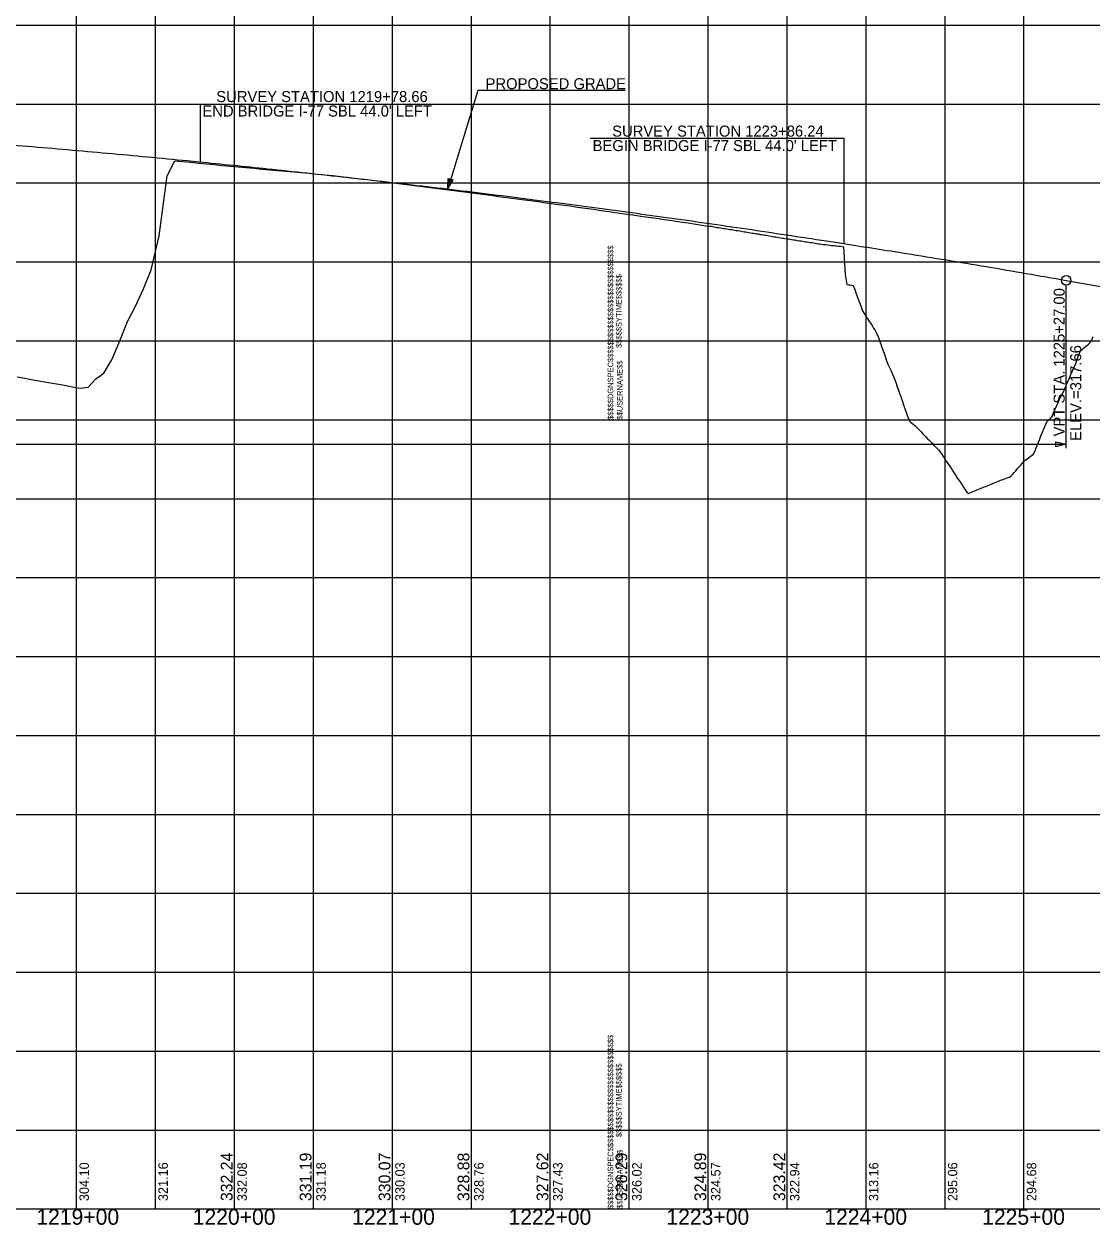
# Model space of a CAD drawing. Extents: x -90830 to 2015517, y -20856 to 836331.
# Drawn here: x 10790 to 11467, y -10807 to -10046 of the extents above; entities that cross this region are included whole.
import ezdxf

# ---------------------------------------------------------------- set-up
doc = ezdxf.new("R2010")
doc.units = 0
for name, color, linetype in [('Level 1', 7, 'Continuous'), ('RD_DDB_Profile_Elev', 7, 'Continuous'), ('RD_DDB_Profile_EX', 7, 'Continuous'), ('RD_DDB_Profile_Lbl', 7, 'Continuous'), ('RD_DDB_Profile_PR', 7, 'Continuous'), ('RD_DDB_StaTX', 7, 'Continuous'), ('RD_DDB_StripGrade', 7, 'Continuous'), ('RD_DDB_VCLbl', 7, 'Continuous'), ('RD_GPK_Profile_Cell', 7, 'Continuous'), ('RD_PD_Final_TX', 7, 'Continuous'), ('RD_TX_Drainage', 7, 'Continuous')]:
    doc.layers.add(name, color=color, linetype=linetype)

msp = doc.modelspace()

# ---------------------------------------------------------------- linework, layer by layer
at = {"layer": 'Level 1'}
for p, q in [((10823.46, -9797.12), (10823.46, -10297.12)), ((10873.46, -9797.12), (10873.46, -10297.12)), ((10923.46, -9797.12), (10923.46, -10297.12)), ((10973.46, -9797.12), (10973.46, -10297.12)), ((11023.46, -9797.12), (11023.46, -10297.12)), ((11073.46, -9797.12), (11073.46, -10297.12)), ((11123.46, -9797.12), (11123.46, -10297.12)), ((11173.46, -9797.12), (11173.46, -10297.12)), ((11173.46, -9797.12), (11173.46, -10297.12)), ((11173.46, -9797.12), (11173.46, -10297.12)), ((11223.46, -9797.12), (11223.46, -10297.12)), ((11273.46, -9797.12), (11273.46, -10297.12)), ((11323.46, -9797.12), (11323.46, -10297.12)), ((11373.46, -9797.12), (11373.46, -10297.12)), ((11423.46, -9797.12), (11423.46, -10297.12)), ((9573.46, -10047.12), (11173.46, -10047.12)), ((11173.46, -10047.12), (12773.46, -10047.12)), ((9573.46, -10097.12), (11173.46, -10097.12)), ((11173.46, -10097.12), (12773.46, -10097.12)), ((9573.46, -10147.12), (11173.46, -10147.12)), ((11173.46, -10147.12), (12773.46, -10147.12)), ((9573.46, -10197.12), (11173.46, -10197.12)), ((11173.46, -10197.12), (12773.46, -10197.12)), ((9573.46, -10247.12), (11173.46, -10247.12)), ((11173.46, -10247.12), (12773.46, -10247.12)), ((9573.46, -10297.12), (11173.46, -10297.12)), ((9573.46, -10297.12), (11173.46, -10297.12)), ((10823.46, -10297.12), (10823.46, -10797.12)), ((10873.46, -10297.12), (10873.46, -10797.12)), ((10923.46, -10297.12), (10923.46, -10797.12)), ((10973.46, -10297.12), (10973.46, -10797.12)), ((11023.46, -10297.12), (11023.46, -10797.12)), ((11073.46, -10297.12), (11073.46, -10797.12)), ((11123.46, -10297.12), (11123.46, -10797.12)), ((11173.46, -10297.12), (11173.46, -10797.12)), ((11173.46, -10297.12), (11173.46, -10797.12)), ((11173.46, -10297.12), (12773.46, -10297.12)), ((11173.46, -10297.12), (12773.46, -10297.12)), ((11173.46, -10297.12), (11173.46, -10797.12)), ((11223.46, -10297.12), (11223.46, -10797.12)), ((11273.46, -10297.12), (11273.46, -10797.12)), ((11323.46, -10297.12), (11323.46, -10797.12)), ((11373.46, -10297.12), (11373.46, -10797.12)), ((11423.46, -10297.12), (11423.46, -10797.12)), ((9573.46, -10347.12), (11173.46, -10347.12)), ((11173.46, -10347.12), (12773.46, -10347.12)), ((9573.46, -10397.12), (11173.46, -10397.12)), ((11173.46, -10397.12), (12773.46, -10397.12)), ((9573.46, -10447.12), (11173.46, -10447.12)), ((11173.46, -10447.12), (12773.46, -10447.12)), ((9573.46, -10497.12), (11173.46, -10497.12)), ((11173.46, -10497.12), (12773.46, -10497.12)), ((9573.46, -10547.12), (11173.46, -10547.12)), ((11173.46, -10547.12), (12773.46, -10547.12)), ((9573.46, -10597.12), (11173.46, -10597.12)), ((11173.46, -10597.12), (12773.46, -10597.12)), ((9573.46, -10647.12), (11173.46, -10647.12)), ((11173.46, -10647.12), (12773.46, -10647.12)), ((9573.46, -10697.12), (11173.46, -10697.12)), ((11173.46, -10697.12), (12773.46, -10697.12)), ((9573.46, -10747.12), (11173.46, -10747.12)), ((11173.46, -10747.12), (12773.46, -10747.12)), ((9573.46, -10797.12), (11173.46, -10797.12)), ((11173.46, -10797.12), (12773.46, -10797.12))]:
    msp.add_line(p, q, dxfattribs=at)
at = {"layer": 'RD_DDB_Profile_EX'}
for points in [[(10785.95, -10270.03), (10790.95, -10270.85), (10795.95, -10271.77), (10800.95, -10272.7), (10805.95, -10273.55), (10810.95, -10274.39), (10815.95, -10275.27), (10820.95, -10276.19), (10825.95, -10277.02), (10830.95, -10276.53), (10835.95, -10271.22), (10840.95, -10267.62), (10845.95, -10259.08), (10850.95, -10247.21), (10855.95, -10234.96), (10860.95, -10225.23), (10865.95, -10214.2), (10870.95, -10202.1), (10875.95, -10180.59), (10880.95, -10142.52), (10885.95, -10133), (10890.95, -10133.5), (10895.95, -10134), (10900.95, -10134.51), (10905.95, -10135.01), (10910.95, -10135.49), (10915.95, -10135.98), (10920.95, -10136.47), (10925.95, -10136.94), (10930.95, -10137.4), (10935.95, -10137.84), (10940.95, -10138.29), (10945.95, -10138.74), (10950.95, -10139.17), (10955.95, -10139.61), (10960.95, -10140.04), (10965.95, -10140.5), (10970.95, -10140.98), (10975.95, -10141.47), (10980.95, -10141.97), (10985.95, -10142.48), (10990.95, -10143.06), (10995.95, -10143.63), (11000.95, -10144.2), (11005.95, -10144.78), (11010.95, -10145.4), (11015.95, -10146.02), (11020.95, -10146.66), (11025.95, -10147.29), (11030.95, -10147.91), (11035.95, -10148.54), (11040.95, -10149.16), (11045.95, -10149.78)], [(11045.95, -10149.78), (11050.95, -10150.42), (11055.95, -10151.06), (11060.95, -10151.7), (11065.95, -10152.35), (11070.95, -10152.99), (11075.95, -10153.63), (11080.95, -10154.27), (11085.95, -10154.92), (11090.95, -10155.58), (11095.95, -10156.24), (11100.95, -10156.91), (11105.95, -10157.57), (11110.95, -10158.25), (11115.95, -10158.92), (11120.95, -10159.6), (11125.95, -10160.29), (11130.95, -10160.98), (11135.95, -10161.67), (11140.95, -10162.37), (11145.95, -10163.07), (11150.95, -10163.78), (11155.95, -10164.5), (11160.95, -10165.23), (11165.95, -10165.95), (11170.95, -10166.66), (11175.95, -10167.36), (11180.95, -10168.05), (11185.95, -10168.75), (11190.95, -10169.46), (11195.95, -10170.19), (11200.95, -10170.92), (11205.95, -10171.66), (11210.95, -10172.41), (11215.95, -10173.2), (11223.46, -10174.38)], [(11223.46, -10174.29), (11224.46, -10174.44), (11225.46, -10174.58), (11226.46, -10174.79), (11227.46, -10174.98), (11228.46, -10175.09), (11229.46, -10175.22), (11230.46, -10175.43), (11231.46, -10175.59), (11232.46, -10175.71), (11233.46, -10175.89), (11234.46, -10176.04), (11235.46, -10176.18), (11236.46, -10176.33), (11237.46, -10176.53), (11238.46, -10176.68), (11239.46, -10176.87), (11240.46, -10177.02), (11241.46, -10177.16), (11242.46, -10177.32), (11243.46, -10177.41), (11244.46, -10177.61), (11245.46, -10177.95), (11246.46, -10178.05), (11247.46, -10178.1), (11248.46, -10178.34), (11249.46, -10178.45), (11250.46, -10178.68), (11251.46, -10178.83), (11252.46, -10178.94), (11253.46, -10179.13), (11254.46, -10179.28), (11255.46, -10179.44), (11256.46, -10179.67), (11257.46, -10179.79), (11258.46, -10179.93), (11259.46, -10180.16), (11260.46, -10180.28), (11261.46, -10180.47), (11262.46, -10180.63), (11263.46, -10180.85), (11264.46, -10180.99), (11265.46, -10181.16), (11266.46, -10181.32), (11267.46, -10181.47), (11268.46, -10181.63), (11269.46, -10181.83), (11270.46, -10181.99), (11271.46, -10182.08), (11272.46, -10182.24), (11273.46, -10182.42), (11274.46, -10182.61), (11275.46, -10182.74), (11276.46, -10182.87), (11277.46, -10183.09), (11278.46, -10183.24), (11279.46, -10183.43), (11280.46, -10183.57), (11281.46, -10183.71), (11282.46, -10183.82), (11283.46, -10184.01), (11284.46, -10184.16), (11285.46, -10184.31), (11286.46, -10184.49), (11287.46, -10184.6), (11288.46, -10184.78), (11289.46, -10184.88), (11290.46, -10185.08), (11291.46, -10185.27), (11292.46, -10185.42), (11293.46, -10185.57), (11294.46, -10185.71), (11295.46, -10185.86), (11296.46, -10186), (11297.46, -10186.1), (11298.46, -10186.2), (11299.46, -10186.35), (11300.46, -10186.45), (11301.46, -10186.63), (11302.46, -10186.74), (11303.46, -10186.8), (11304.46, -10186.93), (11305.46, -10186.92), (11306.46, -10187.08), (11307.46, -10187.25), (11308.46, -10187.39), (11309.46, -10187.51), (11310.46, -10205.14), (11311.46, -10211.45), (11312.46, -10211.58), (11313.46, -10211.71), (11314.46, -10211.84), (11315.46, -10211.97), (11316.46, -10214.55), (11317.46, -10217.33), (11318.46, -10220.12), (11319.46, -10222.9), (11320.46, -10225.69), (11321.46, -10228.22), (11322.46, -10229.76), (11323.46, -10231.3)], [(11323.46, -10231.3), (11324.46, -10232.85), (11325.46, -10234.39), (11326.46, -10235.93), (11327.46, -10237.47), (11328.46, -10239.01), (11329.46, -10240.55), (11330.46, -10242.68), (11331.46, -10245.08), (11332.46, -10247.5), (11333.46, -10250.44), (11334.46, -10253.37), (11335.46, -10256.3), (11336.46, -10259.11), (11337.46, -10261.84), (11338.46, -10264.03), (11339.46, -10266.13), (11340.46, -10268.23), (11341.46, -10270.88), (11342.46, -10273.61), (11343.46, -10276.33), (11344.46, -10279.09), (11345.46, -10281.97), (11346.46, -10284.86), (11347.46, -10287.74), (11348.46, -10290.65), (11349.46, -10293.56), (11350.46, -10296.48), (11351.46, -10298.13), (11352.46, -10298.98), (11353.46, -10299.82), (11354.46, -10300.66), (11355.46, -10301.64), (11356.46, -10302.68), (11357.46, -10303.72), (11358.46, -10304.75), (11359.46, -10305.79), (11360.46, -10306.83), (11361.46, -10307.87), (11362.46, -10308.91), (11363.46, -10309.95), (11364.46, -10310.99), (11365.46, -10312.03), (11366.46, -10313.07), (11367.46, -10314.11), (11368.46, -10315.15), (11369.46, -10316.19), (11370.46, -10317.29), (11371.46, -10318.8), (11372.46, -10320.3), (11373.46, -10321.81), (11374.46, -10323.32), (11375.46, -10324.83), (11376.46, -10326.34), (11377.46, -10327.85), (11378.46, -10329.35), (11379.46, -10330.86), (11380.46, -10332.37), (11381.46, -10333.88), (11382.46, -10335.39), (11383.46, -10336.89), (11384.46, -10338.4), (11385.46, -10339.91), (11386.46, -10341.42), (11387.46, -10342.92), (11388.46, -10343.94), (11389.46, -10343.5), (11390.46, -10343.07), (11391.46, -10342.62), (11392.46, -10342.16), (11393.46, -10341.75), (11394.46, -10341.34), (11395.46, -10340.94), (11396.46, -10340.53), (11397.46, -10340.12), (11398.46, -10339.72), (11399.46, -10339.31), (11400.46, -10338.9), (11401.46, -10338.5), (11402.46, -10338.09), (11403.46, -10337.68), (11404.46, -10337.28), (11405.46, -10336.87), (11406.46, -10336.46), (11407.46, -10336.05), (11408.46, -10335.65), (11409.46, -10335.25), (11410.46, -10334.88), (11411.46, -10334.51), (11412.46, -10334.15), (11413.46, -10333.78), (11414.46, -10333.42), (11415.46, -10332.93), (11416.46, -10331.78), (11417.46, -10330.63), (11418.46, -10329.47), (11419.46, -10328.32), (11420.46, -10327.17), (11421.46, -10326.02), (11422.46, -10324.86), (11423.46, -10323.71)], [(11423.46, -10323.71), (11424.46, -10322.75), (11425.46, -10322.03), (11426.46, -10321.3), (11427.46, -10320.58), (11428.46, -10319.85), (11429.46, -10319.12), (11430.46, -10317.33), (11431.46, -10314.84), (11432.46, -10312.36), (11433.46, -10309.87), (11434.46, -10307.39), (11435.46, -10304.9), (11436.46, -10302.42), (11437.46, -10299.93), (11438.46, -10297.97), (11439.46, -10297.19), (11440.46, -10296.41), (11441.46, -10295.07), (11442.46, -10292.75), (11443.46, -10290.42), (11444.46, -10288.1), (11445.46, -10285.78), (11446.46, -10283.48), (11447.46, -10281.75), (11448.46, -10279.85), (11449.46, -10277.55), (11450.46, -10275.25), (11451.46, -10272.96), (11452.46, -10270.66), (11453.46, -10268.36), (11454.46, -10266.06), (11455.46, -10263.76), (11456.46, -10261.46), (11457.46, -10258.8), (11458.46, -10256.1), (11459.46, -10253.48), (11460.46, -10252.63), (11461.46, -10251.78), (11462.46, -10250.93), (11463.46, -10250.09), (11464.46, -10249.24), (11465.46, -10248.39), (11466.46, -10247.15), (11467.46, -10244.4)]]:
    msp.add_lwpolyline(points, dxfattribs=at)
at = {"layer": 'RD_DDB_Profile_Lbl'}
for p, q in [((10902.12, -10097.12), (11053.25, -10097.12)), ((10902.12, -10133.67), (10902.12, -10097.12)), ((11148.92, -10118.75), (11309.7, -10118.75)), ((11309.7, -10185.54), (11309.7, -10118.75))]:
    msp.add_line(p, q, dxfattribs=at)
at = {"layer": 'RD_DDB_Profile_PR'}
msp.add_line((11450.46, -10208.8), (11473.43, -10212.82), dxfattribs=at)
for points in [[(10543.1, -10107.4), (10590.26, -10109.84), (10640.86, -10112.8), (10691.46, -10116.12), (10742.06, -10119.8), (10792.66, -10123.83), (10843.26, -10128.22), (10893.86, -10132.97), (10901.04, -10133.67)], [(10901.04, -10133.67), (10944.46, -10138.08), (10995.06, -10143.54), (11045.66, -10149.36), (11096.26, -10155.54), (11146.86, -10162.08), (11197.46, -10168.97), (11248.06, -10176.22), (11298.66, -10183.83), (11309.7, -10185.54)], [(11309.7, -10185.54), (11349.26, -10191.79), (11399.86, -10200.12), (11450.46, -10208.8)]]:
    msp.add_spline(points, degree=3, dxfattribs=at)
at = {"layer": 'RD_DDB_VCLbl'}
for p, q in [((11450.46, -10315.16), (11450.46, -10211.8)), ((8920.46, -10312.66), (11450.46, -10312.66))]:
    msp.add_line(p, q, dxfattribs=at)
msp.add_circle((11450.46, -10208.8), 3, dxfattribs=at)
at = {"layer": 'RD_GPK_Profile_Cell'}
msp.add_line((4823.46, -10797.12), (75223.46, -10797.12), dxfattribs=at)
at = {"layer": 'RD_PD_Final_TX'}
for p, q in [((11058.69, -10150.92), (11059.03, -10144.25)), ((11060.58, -10144.72), (11058.69, -10150.92)), ((11058.69, -10150.92), (11062.13, -10145.19)), ((11059.03, -10144.25), (11062.13, -10145.19))]:
    msp.add_line(p, q, dxfattribs=at)
for points in [[(11171.13, -10088.55), (11077.74, -10088.55), (11058.69, -10150.92)], [(11060.51, -10144.78), (11058.75, -10150.55), (11060.48, -10144.73), (11058.78, -10150.27), (11060.41, -10144.74), (11058.78, -10150.07), (11060.33, -10144.73), (11058.79, -10149.84), (11060.27, -10144.7), (11058.81, -10149.48), (11060.19, -10144.66), (11058.84, -10149.1), (11060.1, -10144.66), (11058.86, -10148.81), (11060.04, -10144.63), (11058.88, -10148.48), (11059.97, -10144.64), (11058.9, -10148.19), (11059.92, -10144.57), (11058.9, -10147.94), (11059.82, -10144.57), (11058.92, -10147.58), (11059.75, -10144.54), (11058.96, -10147.14), (11059.67, -10144.5), (11058.94, -10146.84), (11059.6, -10144.48), (11058.97, -10146.39), (11059.51, -10144.48), (11059.01, -10146.02), (11059.43, -10144.41), (11059.02, -10145.7), (11059.36, -10144.42), (11059.03, -10145.41), (11059.3, -10144.36), (11059.06, -10145.05), (11059.22, -10144.39), (11059.08, -10144.65), (11059.13, -10144.39)], [(11058.85, -10150.53), (11060.6, -10144.81), (11058.96, -10150.34), (11060.68, -10144.83), (11059.05, -10150.16), (11060.74, -10144.82), (11059.17, -10150), (11060.78, -10144.85), (11059.3, -10149.8), (11060.85, -10144.86), (11059.42, -10149.61), (11060.9, -10144.88), (11059.55, -10149.38), (11060.97, -10144.88), (11059.71, -10149.11), (11061.06, -10144.92), (11059.84, -10148.87), (11061.12, -10144.91), (11059.98, -10148.62), (11061.18, -10144.95), (11060.14, -10148.39), (11061.24, -10144.96), (11060.29, -10148.12), (11061.28, -10145.02), (11060.49, -10147.78), (11061.35, -10145.01), (11060.65, -10147.56), (11061.41, -10145), (11060.83, -10147.27), (11061.47, -10145.05), (11060.98, -10146.96), (11061.54, -10145.08), (11061.12, -10146.72), (11061.61, -10145.15), (11061.29, -10146.51), (11061.66, -10145.16), (11061.47, -10146.15), (11061.76, -10145.14), (11061.58, -10145.95), (11061.87, -10145.17), (11061.71, -10145.82), (11061.95, -10145.26), (11062.03, -10145.22), (11061.92, -10145.26)]]:
    msp.add_lwpolyline(points, dxfattribs=at)
at = {"layer": 'RD_TX_Drainage'}
msp.add_lwpolyline([(11443.86, -10311.01), (11450.46, -10312.66), (11443.86, -10314.31)], close=True, dxfattribs=at)

# ---------------------------------------------------------------- texts
at = {"layer": 'Level 1'}
for s, p in [('$$$$$DGNSPEC$$$$$$$$$$$$$$$$$$$$$$$$$$$$', (11163.56, -10297.17)), ('$$$$$SYTIME$$$$$$', (11168.86, -10251.57)), ('$$USERNAME$$', (11169.46, -10297.02)), ('$$$$$DGNSPEC$$$$$$$$$$$$$$$$$$$$$$$$$$$$', (11163.56, -10797.17)), ('$$$$$SYTIME$$$$$$', (11168.86, -10751.57)), ('$$USERNAME$$', (11169.46, -10797.02))]:
    msp.add_text(s, height=3.5436, rotation=90, dxfattribs=at).set_placement(p)
at = {"layer": 'RD_DDB_Profile_Elev'}
for s, p in [('332.24', (10922.46, -10792.12)), ('331.19', (10972.46, -10792.12)), ('330.07', (11022.46, -10792.12)), ('328.88', (11072.46, -10792.12)), ('327.62', (11122.46, -10792.12)), ('326.29', (11172.46, -10792.12)), ('324.89', (11222.46, -10792.12)), ('323.42', (11272.46, -10792.12))]:
    msp.add_text(s, height=7.5, rotation=90, dxfattribs=at).set_placement(p)
at = {"layer": 'RD_DDB_Profile_Lbl'}
for s, p in [('SURVEY STATION 1219+78.66', (10912.11, -10095.86)), ("END BRIDGE I-77 SBL 44.0' LEFT", (10903.35, -10105.03)), ('SURVEY STATION 1223+86.24', (11162.86, -10117.75)), ("BEGIN BRIDGE I-77 SBL 44.0' LEFT", (11150.48, -10126.93))]:
    msp.add_text(s, height=7, dxfattribs=at).set_placement(p)
at = {"layer": 'RD_DDB_StaTX'}
for s, p in [('1219+00', (10798.17, -10807.12)), ('1220+00', (10897.21, -10807.12)), ('1221+00', (10998.17, -10807.12)), ('1222+00', (11097.21, -10807.12)), ('1223+00', (11197.21, -10807.12)), ('1224+00', (11297.21, -10807.12)), ('1225+00', (11397.21, -10807.12))]:
    msp.add_text(s, height=10, dxfattribs=at).set_placement(p)
at = {"layer": 'RD_DDB_StripGrade'}
for s, height, p in [(' VPT STA. 1225+27.00 ', 7, (11449.46, -10310.27)), ('ELEV.=317.66', 7, (11459.96, -10310.47)), ('304.10', 6, (10831.46, -10792.12)), ('321.16', 6, (10881.46, -10792.12)), ('332.08', 6, (10931.46, -10792.12)), ('331.18', 6, (10981.46, -10792.12)), ('330.03', 6, (11031.46, -10792.12)), ('328.76', 6, (11081.46, -10792.12)), ('327.43', 6, (11131.46, -10792.12)), ('326.02', 6, (11181.46, -10792.12)), ('324.57', 6, (11231.46, -10792.12)), ('322.94', 6, (11281.46, -10792.12)), ('313.16', 6, (11331.46, -10792.12)), ('295.06', 6, (11381.46, -10792.12)), ('294.68', 6, (11431.46, -10792.12))]:
    msp.add_text(s, height=height, rotation=90, dxfattribs=at).set_placement(p)
at = {"layer": 'RD_PD_Final_TX'}
msp.add_text('PROPOSED GRADE', height=7, dxfattribs=at).set_placement((11082.68, -10087.72))

doc.saveas('drawing.dxf')
